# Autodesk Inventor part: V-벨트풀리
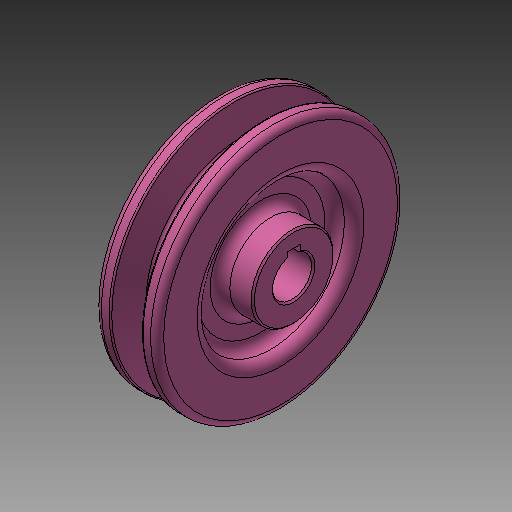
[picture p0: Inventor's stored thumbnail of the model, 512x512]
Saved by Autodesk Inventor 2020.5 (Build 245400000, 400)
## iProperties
Created: 2015-11
Part Number: V-벨트풀리
Material: 강철, 탄소
Document SubType Name: Modeling
Designer: mduedu
Density: 1 g/cm^3
Appearance: 분홍색
Author: mduedu
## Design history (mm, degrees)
sketch "스케치1"
  geometry: L1 (-9.5, 0)-(9.5, 0); L2 (0, 0)-(0, 37.7); L3 (-4.825, 37.7)-(-9.5, 37.7); L4 (-9.5, 37.7)-(-9.5, 0); L5 (0, 28.7)-(-2.074, 28.7); L6 (-2.074, 28.7)-(-4.825, 37.7); L7 (4.825, 37.7)-(9.5, 37.7); L8 (9.5, 37.7)-(9.5, 0); L9 (0, 28.7)-(2.074, 28.7); L10 (2.074, 28.7)-(4.825, 37.7); L11 (-9.5, 35)-(9.5, 35); 3 further points
  constraints: 22 end point, 7 point on line, 4 perpendicular, 3 symmetric about line, 1 coincident, 1 horizontal, 1 horizontal alignment, 1 midpoint, 1 vertical
  dimensions: "d0" = 19 distance of L1.start L1.end; "d2" = 75.4 diameter of L2.end L1 (derived); "d3" = 34 deg angle of L10 L6; "d4" = 6.3 distance between parallel lines of L11 L9; "d5" = 2.7 distance between parallel lines of L7 L11; "d6" = 8 distance of point (4, 35) point (-4, 35); "d7" = 70 diameter of L11 L1
revolve "회전1" sketch "스케치1" stored, may be unused: angle "d8" = 90 deg
sketch "스케치2"
  geometry: C1 r 22.5 at (0, 0); C2 r 12.5 at (0, 0); C3 r 37.7 at (0, 0) reference; 1 further point
  constraints: 2 centre point, 2 coincident
  dimensions: "d35" = 15.2 radial gap between concentric circles of C3 C1 (computed from d5); "d36" = 10 radial gap between concentric circles of C1 C2
extrude "돌출1" cut sketch "스케치2" distance "d11" = 6; taper "d12" = 0 deg
fillet "모깎기1" dims "d13" = 3
feature "면 이동1"
fillet "모깎기2" dims "d14" = 3
fillet "모깎기3" dims "d15" = 1, "d16" = 0.5, "d17" = 2
hole "구멍1" diameter "d20" = 12; stored, may be unused: countersink angle "d24" = 90 deg, drill point angle "d26" = 118 deg; dims "d21" = 6, "d22" = 4, "d23" = 2, "d25" = 8, "d37" = 10, "d38" = 10
sketch "스케치3"
  geometry: L1 (-2, 0)-(2, 0); L2 (2, 0)-(2, 7.8); L3 (2, 7.8)-(-2, 7.8); L4 (-2, 7.8)-(-2, 0); C1 r 12.5 at (0, 0) reference; 2 further points
  constraints: 8 end point, 2 coincident, 2 parallel, 1 horizontal, 1 midpoint, 1 perpendicular
  dimensions: "d27" = 4 distance of L2.end L3.end; "d29" = 7.8 distance of L3.end L1.start
extrude "돌출2" cut sketch "스케치3" extent not by distance; stored distance "d30" = 6; taper "d31" = 0 deg
chamfer "모따기1" distance "d32" = 0.5; stored, may be unused: second distance "d33" = 2, angle "d34" = 45 deg
node "솔리드1"
mirror "대칭1"
